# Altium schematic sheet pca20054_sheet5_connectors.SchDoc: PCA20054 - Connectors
size A3; Organization: Nordic Semiconductor; DocumentNumber: 1; Revision: 1.0.0; SheetNumber: 5; SheetTotal: 5; Date: 2020-02-07; CompanyName: Nordic Semiconductor; DrawnBy: KJP; ProjectNumber: 4467
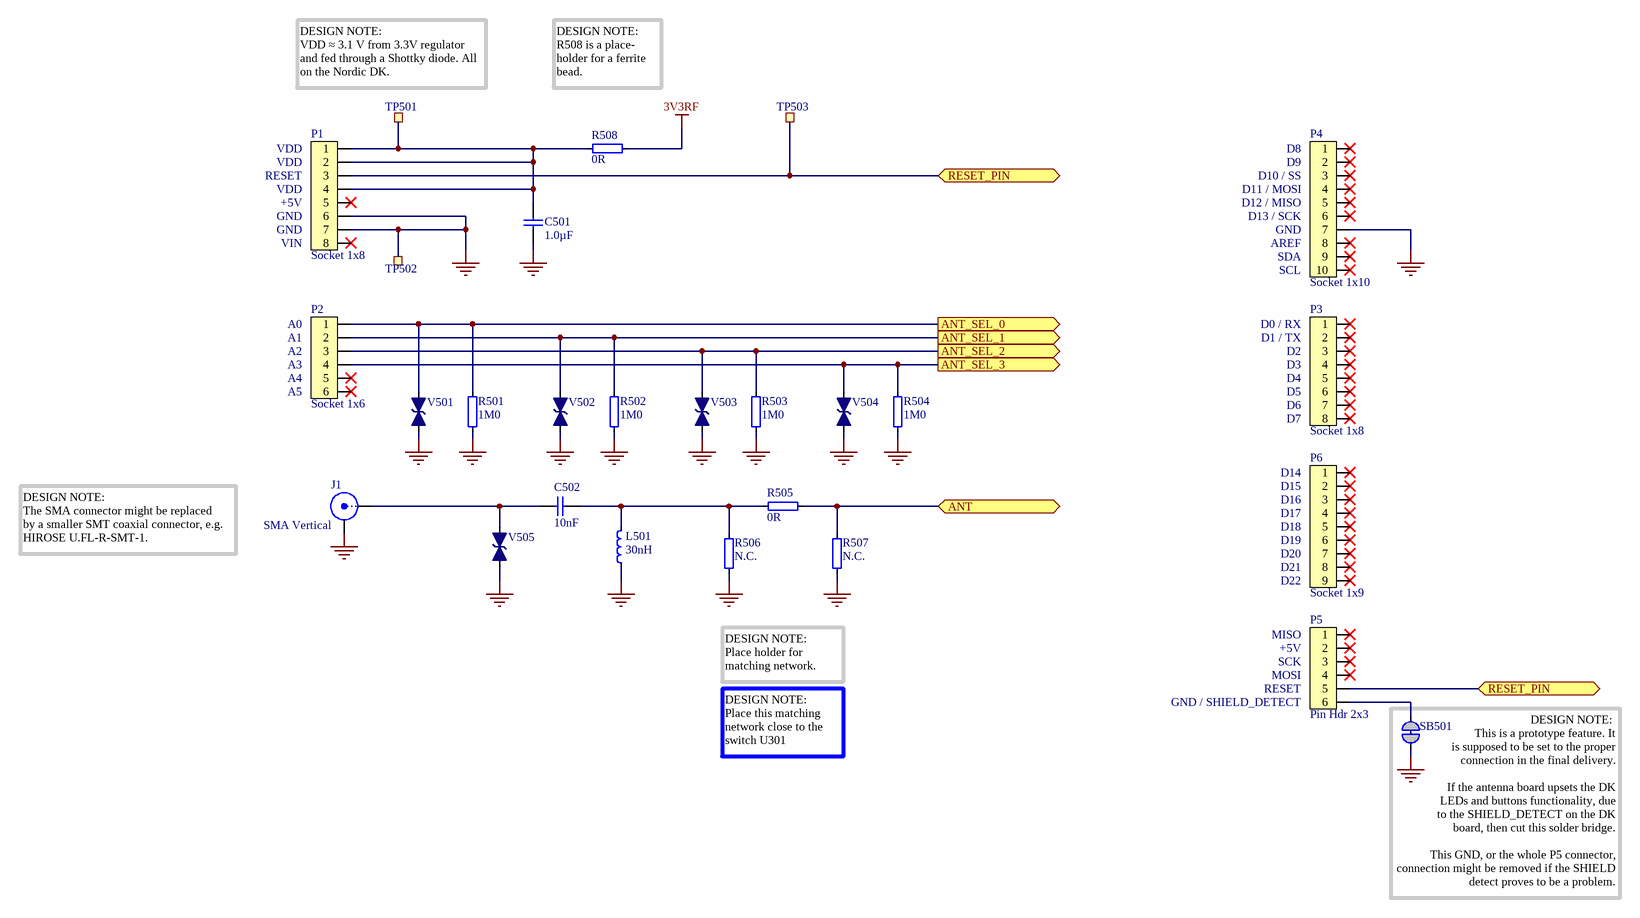
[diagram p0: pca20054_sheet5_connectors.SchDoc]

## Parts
C501  1.0µF  [CAPC1608X06L]
C502  10nF  [CAPC1005X04L]
J1  SMA Vertical  [CON_SMA_COAX_FEM_STRAIGHT_5P_1]
L501  30nH  [INDC1005X04L_WW]
P1  Socket 1x8  [SOCKET_1x8_SMD]
P2  Socket 1x6  [SOCKET_1x6_SMD]
P3  Socket 1x8  [SOCKET_1x8_SMD]
P4  Socket 1x10  [SOCKET_1x10_SMD]
P5  Pin Hdr 2x3  [HDR_2x3-SMD]
P6  Socket 1x9  [SOCKET_1x9_SMD]
R501  1M0  [RESC1005X04L]
R502  1M0  [RESC1005X04L]
R503  1M0  [RESC1005X04L]
R504  1M0  [RESC1005X04L]
R505  0R  [RESC1005X04L]
R506  N.C.  [RESC1005X04L_NC]
R507  N.C.  [RESC1005X04L_NC]
R508  0R  [RESC1005X04L]
SB501  Solderbridge  [Solderbridge_Shorted_Power]  (value not drawn)  (net tie, no BOM)
TP501  Ø1.0mm,SMD  [TP_SMD_Ø1.0mm]  (value not drawn)  (no BOM)
TP502  Ø1.0mm,SMD  [TP_SMD_Ø1.0mm]  (value not drawn)  (no BOM)
TP503  Ø1.0mm,SMD  [TP_SMD_Ø1.0mm]  (value not drawn)  (no BOM)
V501  LXES15AAA1-133  [RESC1005X04L]  (value not drawn)
V502  LXES15AAA1-133  [RESC1005X04L]  (value not drawn)
V503  LXES15AAA1-133  [RESC1005X04L]  (value not drawn)
V504  LXES15AAA1-133  [RESC1005X04L]  (value not drawn)
V505  LXES15AAA1-133  [RESC1005X04L]  (value not drawn)

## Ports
ANT (bidir), ANT_SEL_0 (out), ANT_SEL_1 (out), ANT_SEL_2 (out), ANT_SEL_3 (out), RESET_PIN (bidir)

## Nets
3V3RF: R508.2
GND: C501.1 J1.2(Y) L501.1 P1.6 P1.7 P4.7 R501.1 R502.1 R503.1 R504.1 R506.1 R507.1 SB501.2 TP502.1 V501.2 V502.2 V503.2 V504.2 V505.2
ANT: R505.2 R507.2 ; port ANT
ANT_SEL_0: P2.1 R501.2 V501.1 ; port ANT_SEL_0
ANT_SEL_1: P2.2 R502.2 V502.1 ; port ANT_SEL_1
ANT_SEL_2: P2.3 R503.2 V503.1 ; port ANT_SEL_2
ANT_SEL_3: P2.4 R504.2 V504.1 ; port ANT_SEL_3
RESET_PIN: P1.3 P5.5 TP503.1 ; port RESET_PIN
NetC501_2: C501.2 P1.1 P1.2 P1.4 R508.1 TP501.1
NetC502_1: C502.1 L501.2 R505.1 R506.2
NetC502_2: C502.2 J1.1(X) V505.1
NetP5_6: P5.6 SB501.1

Not connected (* = marked no-connect by the designer): P1 5* 8*; P2 5* 6*; P3 1* 2* 3* 4* 5* 6* 7* 8*; P4 1* 2* 3* 4* 5* 6* 8* 9* 10*; P5 1* 2* 3* 4*; P6 1* 2* 3* 4* 5* 6* 7* 8* 9*

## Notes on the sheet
- (near TP501) DESIGN NOTE:
  VDD ≈ 3.1 V from 3.3V regulator and fed through a Shottky diode. All on the Nordic DK.
- DESIGN NOTE:
  R508 is a place-
  holder for a ferrite bead.
- (near P1) VDD
- (near P1) RESET
- (near P4) D8
- (near P4) D9
- (near P4) D10 / SS
- (near P4) D11 / MOSI
- (near P1) +5V
- (near P1) GND
- (near P1) VIN
- (near P4) D12 / MISO
- (near P4) D13 / SCK
- (near P4) GND
- (near P4) AREF
- (near P4) SDA
- (near P4) SCL
- (near P2) A0
- (near P3) D0 / RX
- (near P2) A1
- (near P2) A2
- (near P2) A3
- (near P2) A4
- (near P2) A5
- (near P3) D1 / TX
- (near P3) D2
- (near P3) D3
- (near P3) D4
- (near P3) D5
- (near P3) D6
- (near P3) D7
- (near P6) D14
- (near P6) D15
- (near P6) D16
- (near P6) D17
- (near P6) D18
- (near P6) D19
- DESIGN NOTE:
  The SMA connector might be replaced
  by a smaller SMT coaxial connector, e.g.
  HIROSE U.FL-R-SMT-1.
- (near P6) D20
- (near P6) D21
- (near P6) D22
- (near P5) MISO
- (near P5) +5V
- (near P5) SCK
- (near P5) MOSI
- DESIGN NOTE:
  Place holder for matching network.
- (near P5) RESET
- (near P5) GND / SHIELD_DETECT
- DESIGN NOTE:
  Place this matching network close to the switch U301
- (near SB501) DESIGN NOTE:
  This is a prototype feature. It
  is supposed to be set to the proper
  connection in the final delivery.
  If the antenna board upsets the DK
  LEDs and buttons functionality, due
  to the SHIELD_DETECT on the DK
  board, then cut this solder bridge.
  This GND, or the whole P5 connector, connection might be removed if the SHIELD detect proves to be a problem.

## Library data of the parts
C501 = C0603-1µ0: Capacitor, X7R, ±10%; Part number IPS: 00000000616; Note: 16V; Artikkelnr Noca: 20039282
C502 = C0402-10n: Capacitor, X7R, ±10%; Part number IPS: 00000007784; Note: 16V; Artikkelnr Noca: 20039166
J1 = SMA-Vert-Std_Sigma: SMA Vertical connector; Artikkelnr Noca: N.A.
L501 = L0402-30n-Wirewound-Murata: Inductor, 270mA, ±2%, 580mΩ, Q=25; Manufacturer: Murata; Manufacturer Part Number: LQW15AN30NG00; Note: -55°C ~ 125°C; Artikkelnr Noca: N.A.
P1 P3 = Socket 1x8 SMD: Socket 1x8, 2.54mm (100mil), SMD; Manufacturer: W-CON; Manufacturer Part Number: 2171-108MS0CUNR1; Part number IPS: 00000009963; Artikkelnr Noca: 55030002
P2 = Socket 1x6 SMD: Socket 1x6, 2.54mm (100mil), SMD; Manufacturer: W-CON; Manufacturer Part Number: 2171-106MS0CUNR1; Part number IPS: 00000009964; Artikkelnr Noca: 55030001
P4 = Socket 1x10 SMD: Socket 1x10, 2.54mm (100mil), SMD; Manufacturer: W-CON; Manufacturer Part Number: 2171-110MS0CUNR1; Part number IPS: 00000009965; Artikkelnr Noca: 55030004
P5 = Pin Header 2x3 SMD: Pin Header 2x3, 2.54mm (100mil) SMD; Manufacturer: W-CON; Manufacturer Part Number: 1125-1203S0M116R1; Part number IPS: 00000009966; Artikkelnr Noca: 55010007
P6 = Socket 1x9 SMD: Socket 1x9, 2.54mm (100mil), SMD; Manufacturer: W-CON; Manufacturer Part Number: 2171-109MS0CUNR1; Part number IPS: N.A.; Artikkelnr Noca: 55030003
R501-R504 = R0402-1M0: Resistor, ±1%, 0.063W; Part number IPS: 00000006807; Note: Chip Res 1%; Artikkelnr Noca: 27049145
R505 R508 = R0402-0R: Resistor, ±5%, 0.063W; Part number IPS: 00000007128; Note: Chip Res 5%; Artikkelnr Noca: 27049000
R506 R507 = R0402-N.C.: Not mounted; Assembly: Not mounted; Note: Chip Res; Artikkelnr Noca: N.A.
SB501 = Solderbridge Shorted Power: Shorted Solderbridge Power; Artikkelnr Noca: N.A.
TP501-TP503 = TP_SMD_Ø1.0MM: 1.0mm circular SMD testpad; Manufacturer: Nordic Semiconductor; Artikkelnr Noca: N.A.
V501-V505 = LXES15AAA1-133: TVS DIODE 15VWM 0402; Manufacturer: Murata; Artikkelnr Noca: N.A.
